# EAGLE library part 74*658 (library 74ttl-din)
Octal bus TRANSCEIVER, 3-state
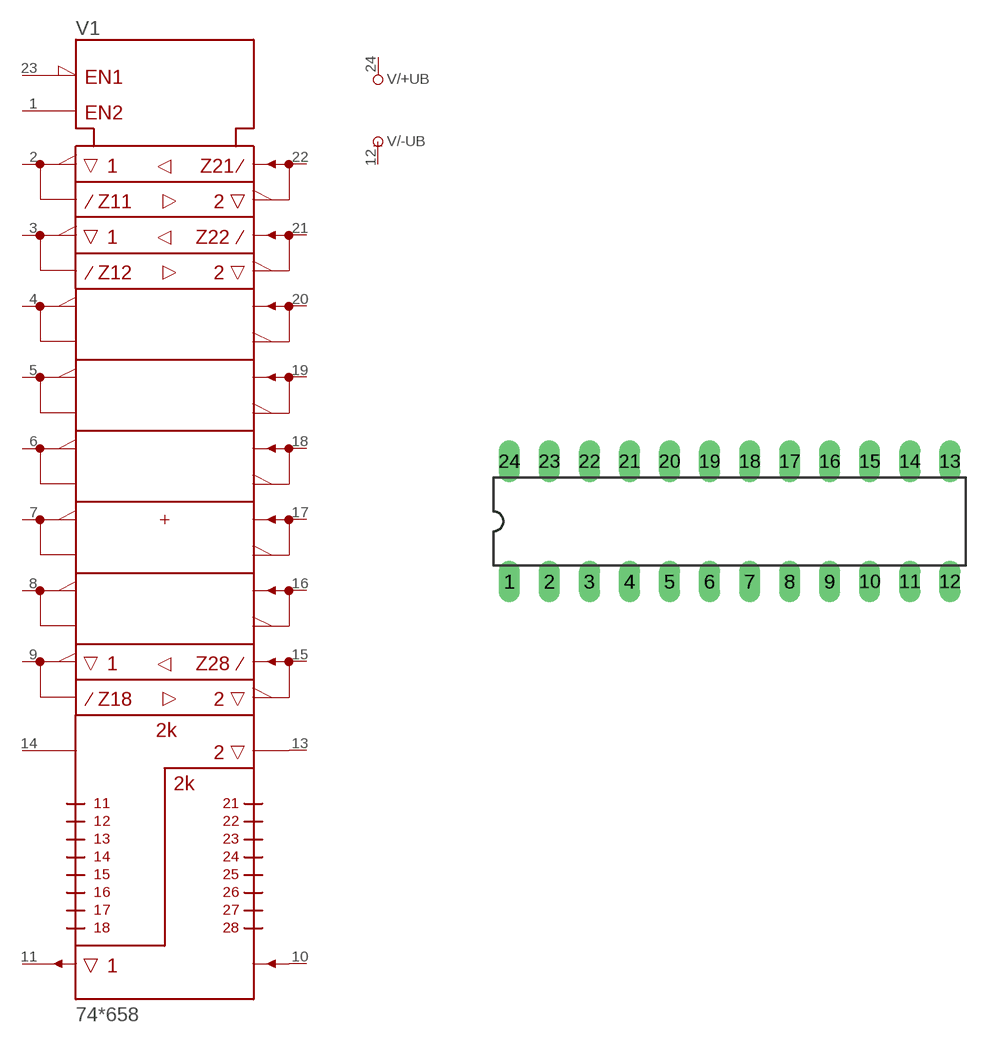
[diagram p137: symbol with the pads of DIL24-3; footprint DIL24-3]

Designator prefix V; gates /+UB=+UB /-UB=-UB 1=658

## 74658N  [DIL24-3]
1  1:GAB  in
2  1:A1
3  1:A2
4  1:A3
5  1:A4
6  1:A5
7  1:A6
8  1:A7
9  1:A8
10  1:BPI  in
11  1:BPO  out
12  /-UB:-UB  pwr
13  1:APO  out
14  1:API  in
15  1:B8
16  1:B7
17  1:B6
18  1:B5
19  1:B4
20  1:B3
21  1:B2
22  1:B1
23  1:G\BA  in
24  /+UB:+UB  pwr

## Footprint DIL24-3 (pad centres in mm)
Dual In Line Package 0.3 inch
drill 0.813 long: 1 -13.97,-3.81; 2 -11.43,-3.81; 3 -8.89,-3.81; 4 -6.35,-3.81; 5 -3.81,-3.81; 6 -1.27,-3.81; 7 1.27,-3.81; 8 3.81,-3.81; 9 6.35,-3.81; 10 8.89,-3.81; 11 11.43,-3.81; 12 13.97,-3.81; 13 13.97,3.81; 14 11.43,3.81; 15 8.89,3.81; 16 6.35,3.81; 17 3.81,3.81; 18 1.27,3.81; 19 -1.27,3.81; 20 -3.81,3.81; 21 -6.35,3.81; 22 -8.89,3.81; 23 -11.43,3.81; 24 -13.97,3.81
